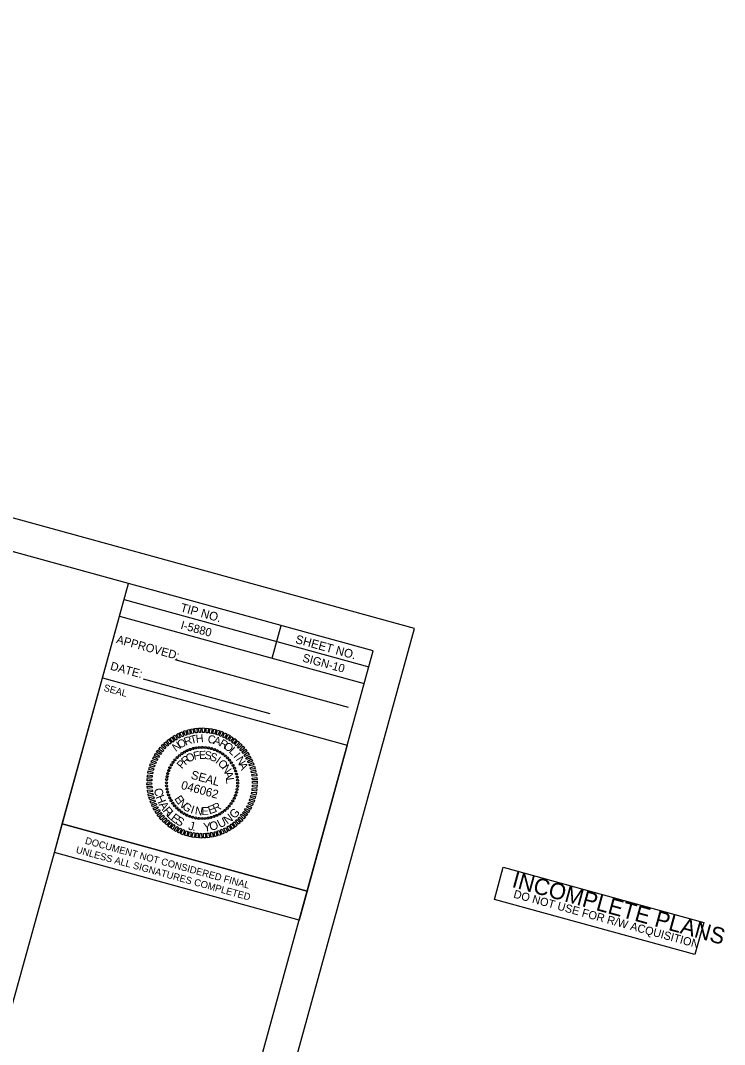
# Model space of a CAD drawing. Extents: x 1641195 to 1643343, y 841291 to 842800.
# Drawn here: x 1642824 to 1643343, y 842045 to 842799 of the extents above; entities that cross this region are included whole.
import ezdxf

# ---------------------------------------------------------------- set-up
doc = ezdxf.new("R2010")
doc.units = 0
for name, color, linetype in [('Default', 7, 'Continuous'), ('Level 11', 7, 'Continuous'), ('Level 18', 7, 'Continuous'), ('Level 2', 7, 'Continuous'), ('Level 3', 7, 'Continuous'), ('Level 6', 7, 'Continuous'), ('Level 60', 7, 'Continuous'), ('Level 8', 7, 'Continuous'), ('Level 9', 7, 'Continuous'), ('MILEMARKERS', 7, 'Continuous')]:
    doc.layers.add(name, color=color, linetype=linetype)

msp = doc.modelspace()

# ---------------------------------------------------------------- linework, layer by layer
at = {"layer": 'Level 18'}
for p, q in [((1642897.06, 842360.4), (1642903.68, 842384.45)), ((1642884.54, 842314.91), (1642897.06, 842360.4)), ((1642854.98, 842207.5), (1642884.54, 842314.91)), ((1643035.24, 842157.8), (1642854.98, 842207.5))]:
    msp.add_line(p, q, dxfattribs=at)
at = {"layer": 'Level 2'}
msp.add_lwpolyline([(1641195.06, 841738.58), (1642822.56, 841290.71), (1643114.42, 842351.28), (1641486.92, 842799.16)], close=True, dxfattribs=at)
at = {"layer": 'Level 3'}
msp.add_lwpolyline([(1643083.96, 842334.84), (1641638.42, 842732.64), (1641359.54, 841719.25), (1642805.09, 841321.44)], close=True, dxfattribs=at)
at = {"layer": 'Level 6'}
msp.add_lwpolyline([(1641792.98, 842690.11), (1641752.38, 842181.83), (1641755.46, 842119.79), (1641627.17, 841958.82), (1641586.62, 841880.3), (1641436.07, 841811.6), (1641408.39, 841755.09), (1641452.55, 841742.94), (1641576.94, 841708.71), (1641653.36, 841687.67), (1641800.35, 841636.49), (1641872.21, 841608.48), (1641936.45, 841597.66), (1642028.27, 841572.39), (1642158.19, 841597.22), (1642252.63, 841714.28), (1642387.32, 841813.32), (1642532.75, 841918.25), (1642817.65, 842071.9), (1642849.16, 842186.32), (1642903.68, 842384.45)], close=True, dxfattribs=at)
at = {"layer": 'Level 60'}
msp.add_lwpolyline([(1643173.29, 842151.82), (1643179.79, 842175.43), (1643327.45, 842134.79), (1643320.96, 842111.18)], close=True, dxfattribs=at)
at = {"layer": 'Level 8'}
for p, q in [((1642849.13, 842186.23), (1642854.96, 842207.41)), ((1642854.96, 842207.41), (1643035.24, 842157.8)), ((1643029.41, 842136.62), (1642849.13, 842186.23)), ((1643035.24, 842157.79), (1643029.41, 842136.61))]:
    msp.add_line(p, q, dxfattribs=at)
at = {"layer": 'Level 9'}
for p, q in [((1642884.54, 842314.91), (1642897.06, 842360.39)), ((1642953.58, 842263.45), (1642953.58, 842263.45)), ((1642955.81, 842263.74), (1642955.81, 842263.74)), ((1642958.09, 842263.8), (1642958.09, 842263.8)), ((1642960.43, 842263.64), (1642960.43, 842263.64)), ((1642962.68, 842263.38), (1642962.68, 842263.38)), ((1642939.48, 842256.27), (1642939.48, 842256.27)), ((1642941.21, 842257.77), (1642941.21, 842257.77)), ((1642943.04, 842259.19), (1642943.04, 842259.19)), ((1642944.96, 842260.37), (1642944.96, 842260.37)), ((1642947.02, 842261.46), (1642947.02, 842261.46)), ((1642949.12, 842262.27), (1642949.12, 842262.27)), ((1642951.34, 842262.94), (1642951.34, 842262.94)), ((1642964.92, 842262.86), (1642964.92, 842262.86)), ((1642967.11, 842262.14), (1642967.11, 842262.14)), ((1642969.2, 842261.22), (1642969.2, 842261.22)), ((1642971.21, 842260.22), (1642971.21, 842260.22)), ((1642973.16, 842258.97), (1642973.16, 842258.97)), ((1642974.95, 842257.54), (1642974.95, 842257.54)), ((1642976.66, 842256.02), (1642976.66, 842256.02)), ((1642934.27, 842248.81), (1642934.27, 842248.81)), ((1642935.28, 842250.82), (1642935.28, 842250.82)), ((1642936.53, 842252.76), (1642936.53, 842252.76)), ((1642937.96, 842254.56), (1642937.96, 842254.56)), ((1642978.16, 842254.28), (1642978.16, 842254.28)), ((1642979.58, 842252.46), (1642979.58, 842252.46)), ((1642980.76, 842250.54), (1642980.76, 842250.54)), ((1642981.85, 842248.48), (1642981.85, 842248.48)), ((1642932.12, 842242.29), (1642932.12, 842242.29)), ((1642932.64, 842244.53), (1642932.64, 842244.53)), ((1642933.36, 842246.72), (1642933.36, 842246.72)), ((1642982.67, 842246.38), (1642982.67, 842246.38)), ((1642983.34, 842244.16), (1642983.34, 842244.16)), ((1642983.84, 842241.92), (1642983.84, 842241.92)), ((1642931.69, 842237.7), (1642931.69, 842237.7)), ((1642931.76, 842235.42), (1642931.76, 842235.42)), ((1642931.86, 842240.03), (1642931.86, 842240.03)), ((1642932.05, 842233.18), (1642932.05, 842233.18)), ((1642957.95, 842237.55), (1642957.95, 842237.55)), ((1642984.03, 842235.07), (1642984.03, 842235.07)), ((1642984.13, 842239.69), (1642984.13, 842239.69)), ((1642984.2, 842237.41), (1642984.2, 842237.41)), ((1642932.55, 842230.95), (1642932.55, 842230.95)), ((1642933.23, 842228.73), (1642933.23, 842228.73)), ((1642934.04, 842226.63), (1642934.04, 842226.63)), ((1642981.62, 842226.3), (1642981.62, 842226.3)), ((1642982.53, 842228.39), (1642982.53, 842228.39)), ((1642983.25, 842230.58), (1642983.25, 842230.58)), ((1642983.78, 842232.82), (1642983.78, 842232.82)), ((1642935.13, 842224.57), (1642935.13, 842224.57)), ((1642936.31, 842222.64), (1642936.31, 842222.64)), ((1642937.73, 842220.82), (1642937.73, 842220.82)), ((1642939.23, 842219.09), (1642939.23, 842219.09)), ((1642976.41, 842218.84), (1642976.41, 842218.84)), ((1642977.93, 842220.55), (1642977.93, 842220.55)), ((1642979.36, 842222.34), (1642979.36, 842222.34)), ((1642980.62, 842224.29), (1642980.62, 842224.29)), ((1642940.94, 842217.57), (1642940.94, 842217.57)), ((1642942.74, 842216.14), (1642942.74, 842216.14)), ((1642944.68, 842214.88), (1642944.68, 842214.88)), ((1642946.69, 842213.88), (1642946.69, 842213.88)), ((1642948.78, 842212.97), (1642948.78, 842212.97)), ((1642950.97, 842212.24), (1642950.97, 842212.24)), ((1642953.21, 842211.72), (1642953.21, 842211.72)), ((1642955.47, 842211.47), (1642955.47, 842211.47)), ((1642957.8, 842211.3), (1642957.8, 842211.3)), ((1642960.08, 842211.36), (1642960.08, 842211.36)), ((1642962.31, 842211.66), (1642962.31, 842211.66)), ((1642964.55, 842212.16), (1642964.55, 842212.16)), ((1642966.77, 842212.83), (1642966.77, 842212.83)), ((1642968.87, 842213.64), (1642968.87, 842213.64)), ((1642970.93, 842214.73), (1642970.93, 842214.73)), ((1642972.85, 842215.92), (1642972.85, 842215.92)), ((1642974.68, 842217.34), (1642974.68, 842217.34))]:
    msp.add_line(p, q, dxfattribs=at)
for points in [[(1642884.54, 842314.91), (1643064.82, 842265.29), (1643035.27, 842157.88), (1642854.98, 842207.5)], [(1642936.32, 842267.72), (1642934.19, 842270.37), (1642935.64, 842271.4), (1642937.26, 842268.45)], [(1642938.58, 842269.19), (1642936.53, 842271.93), (1642938.1, 842272.77), (1642939.6, 842269.79)], [(1642940.71, 842270.53), (1642939.05, 842273.33), (1642940.58, 842274.23), (1642941.85, 842270.99)], [(1642943.14, 842271.58), (1642941.58, 842274.57), (1642943.22, 842275.28), (1642944.27, 842271.99)], [(1642945.45, 842272.61), (1642944.24, 842275.67), (1642945.8, 842276.29), (1642946.72, 842272.93)], [(1642948.01, 842273.3), (1642946.83, 842276.52), (1642948.61, 842276.92), (1642949.12, 842273.66)], [(1642950.5, 842273.96), (1642949.6, 842277.21), (1642951.35, 842277.52), (1642951.73, 842274.13)], [(1642953, 842274.45), (1642952.43, 842277.73), (1642954.11, 842277.94), (1642954.34, 842274.43)], [(1642955.69, 842274.62), (1642955.3, 842277.96), (1642956.99, 842278.01), (1642956.84, 842274.71)], [(1642958.29, 842274.66), (1642958.04, 842278.12), (1642959.85, 842278.04), (1642959.42, 842274.64)], [(1642960.86, 842274.59), (1642960.88, 842278.04), (1642962.59, 842277.76), (1642962.12, 842274.43)], [(1642963.37, 842274.27), (1642963.64, 842277.66), (1642965.42, 842277.42), (1642964.62, 842274.11)], [(1642965.97, 842273.88), (1642966.56, 842277.23), (1642968.22, 842276.75), (1642967.17, 842273.51)], [(1642968.39, 842273.2), (1642969.23, 842276.49), (1642970.89, 842276.01), (1642969.59, 842272.84)], [(1642970.88, 842272.4), (1642971.93, 842275.64), (1642973.52, 842274.91), (1642972.04, 842271.89)], [(1642973.21, 842271.37), (1642974.49, 842274.5), (1642976.1, 842273.81), (1642974.38, 842270.91)], [(1642975.65, 842270.15), (1642977, 842273.31), (1642978.62, 842272.47), (1642976.64, 842269.63)], [(1642977.91, 842268.87), (1642979.47, 842271.82), (1642980.91, 842270.91), (1642978.88, 842268.24)], [(1642928.88, 842260.61), (1642926.04, 842262.58), (1642927.2, 842263.95), (1642929.67, 842261.59)], [(1642930.49, 842262.68), (1642927.93, 842264.69), (1642929.09, 842266.06), (1642931.35, 842263.49)], [(1642932.26, 842264.55), (1642929.82, 842266.79), (1642931.19, 842267.95), (1642933.31, 842265.25)], [(1642934.3, 842266.18), (1642932.01, 842268.61), (1642933.35, 842269.83), (1642935.21, 842266.97)], [(1642979.95, 842267.37), (1642981.94, 842270.27), (1642983.2, 842269.29), (1642981.03, 842266.72)], [(1642981.99, 842265.83), (1642984.02, 842268.49), (1642985.41, 842267.38), (1642982.96, 842264.98)], [(1642984.02, 842264.06), (1642986.13, 842266.6), (1642987.42, 842265.35), (1642984.82, 842263.21)], [(1642985.64, 842262.19), (1642988.17, 842264.67), (1642989.21, 842263.27), (1642986.6, 842261.3)], [(1642924.63, 842254.14), (1642921.59, 842255.35), (1642922.39, 842256.98), (1642925.31, 842255.1)], [(1642925.91, 842256.4), (1642922.94, 842257.87), (1642923.72, 842259.45), (1642926.59, 842257.36)], [(1642927.3, 842258.64), (1642924.39, 842260.36), (1642925.45, 842261.76), (1642928.13, 842259.56)], [(1642987.33, 842260.14), (1642989.92, 842262.44), (1642990.95, 842260.99), (1642988.11, 842259.18)], [(1642988.85, 842258.07), (1642991.6, 842260.17), (1642992.51, 842258.65), (1642989.62, 842257.07)], [(1642990.22, 842255.83), (1642993.01, 842257.66), (1642993.91, 842256.13), (1642990.77, 842254.83)], [(1642921.99, 842246.78), (1642918.65, 842247.47), (1642919.1, 842249.19), (1642922.3, 842247.99)], [(1642922.69, 842249.3), (1642919.42, 842250.24), (1642919.95, 842251.89), (1642923.1, 842250.49)], [(1642923.56, 842251.66), (1642920.4, 842252.8), (1642921.04, 842254.47), (1642924.13, 842252.81)], [(1642991.52, 842253.56), (1642994.44, 842255.24), (1642995.15, 842253.6), (1642991.97, 842252.36)], [(1642992.54, 842251.19), (1642995.56, 842252.68), (1642996.15, 842250.97), (1642992.9, 842250.07)], [(1642993.32, 842248.78), (1642996.5, 842250.01), (1642997.07, 842248.25), (1642993.77, 842247.58)], [(1642920.9, 842239.17), (1642917.46, 842239.03), (1642917.6, 842240.83), (1642920.87, 842240.32)], [(1642921.07, 842241.72), (1642917.59, 842241.86), (1642917.88, 842243.62), (1642921.18, 842242.99)], [(1642921.39, 842244.23), (1642917.99, 842244.67), (1642918.33, 842246.42), (1642921.6, 842245.47)], [(1642994.07, 842246.21), (1642997.36, 842247.25), (1642997.61, 842245.52), (1642994.43, 842245.09)], [(1642994.52, 842243.77), (1642997.9, 842244.52), (1642998.14, 842242.74), (1642994.74, 842242.53)], [(1642994.82, 842241.16), (1642998.25, 842241.68), (1642998.4, 842239.97), (1642995.06, 842239.96)], [(1642920.88, 842236.59), (1642917.34, 842236.25), (1642917.47, 842238), (1642920.8, 842237.74)], [(1642921.07, 842233.95), (1642917.64, 842233.42), (1642917.49, 842235.14), (1642920.84, 842235.14)], [(1642994.82, 842233.38), (1642998.3, 842233.25), (1642998.01, 842231.49), (1642994.72, 842232.12)], [(1642994.99, 842235.93), (1642998.43, 842236.08), (1642998.29, 842234.28), (1642995.02, 842234.79)], [(1642995.01, 842238.52), (1642998.55, 842238.85), (1642998.42, 842237.1), (1642995.09, 842237.36)], [(1642921.37, 842231.33), (1642917.99, 842230.58), (1642917.75, 842232.37), (1642921.15, 842232.58)], [(1642921.83, 842228.9), (1642918.53, 842227.85), (1642918.28, 842229.59), (1642921.46, 842230.01)], [(1642922.57, 842226.33), (1642919.39, 842225.09), (1642918.82, 842226.86), (1642922.12, 842227.53)], [(1642993.21, 842225.81), (1642996.47, 842224.86), (1642995.94, 842223.22), (1642992.79, 842224.62)], [(1642993.91, 842228.33), (1642997.24, 842227.64), (1642996.8, 842225.91), (1642993.59, 842227.11)], [(1642994.51, 842230.87), (1642997.9, 842230.44), (1642997.56, 842228.69), (1642994.29, 842229.63)], [(1642923.35, 842223.92), (1642920.33, 842222.43), (1642919.74, 842224.14), (1642922.99, 842225.03)], [(1642924.37, 842221.55), (1642921.45, 842219.87), (1642920.74, 842221.51), (1642923.92, 842222.75)], [(1642925.67, 842219.27), (1642922.88, 842217.45), (1642921.98, 842218.98), (1642925.12, 842220.28)], [(1642927.04, 842217.03), (1642924.29, 842214.93), (1642923.38, 842216.46), (1642926.27, 842218.04)], [(1642989.98, 842218.7), (1642992.95, 842217.24), (1642992.17, 842215.66), (1642989.3, 842217.74)], [(1642991.26, 842220.96), (1642994.3, 842219.75), (1642993.5, 842218.12), (1642990.58, 842220)], [(1642992.33, 842223.44), (1642995.49, 842222.31), (1642994.85, 842220.64), (1642991.76, 842222.29)], [(1642928.56, 842214.97), (1642925.97, 842212.66), (1642924.94, 842214.12), (1642927.78, 842215.92)], [(1642930.25, 842212.92), (1642927.72, 842210.43), (1642926.68, 842211.83), (1642929.29, 842213.81)], [(1642931.87, 842211.04), (1642929.77, 842208.51), (1642928.47, 842209.76), (1642931.07, 842211.9)], [(1642983.63, 842210.56), (1642986.07, 842208.31), (1642984.7, 842207.16), (1642982.58, 842209.86)], [(1642985.4, 842212.43), (1642987.96, 842210.42), (1642986.8, 842209.05), (1642984.55, 842211.62)], [(1642987.01, 842214.5), (1642989.85, 842212.53), (1642988.69, 842211.15), (1642986.22, 842213.51)], [(1642988.6, 842216.47), (1642991.5, 842214.75), (1642990.44, 842213.35), (1642987.77, 842215.54)], [(1642933.91, 842209.28), (1642931.87, 842206.62), (1642930.48, 842207.73), (1642932.93, 842210.12)], [(1642935.94, 842207.73), (1642933.95, 842204.84), (1642932.69, 842205.81), (1642934.86, 842208.39)], [(1642937.98, 842206.24), (1642936.42, 842203.29), (1642934.98, 842204.2), (1642937.01, 842206.86)], [(1642940.25, 842204.95), (1642938.89, 842201.79), (1642937.28, 842202.64), (1642939.25, 842205.48)], [(1642942.69, 842203.73), (1642941.4, 842200.61), (1642939.79, 842201.29), (1642941.51, 842204.2)], [(1642945.01, 842202.71), (1642943.97, 842199.47), (1642942.37, 842200.2), (1642943.85, 842203.22)], [(1642972.75, 842203.53), (1642974.31, 842200.54), (1642972.67, 842199.82), (1642971.62, 842203.11)], [(1642975.18, 842204.58), (1642976.84, 842201.78), (1642975.31, 842200.87), (1642974.04, 842204.11)], [(1642977.31, 842205.92), (1642979.36, 842203.18), (1642977.79, 842202.34), (1642976.29, 842205.32)], [(1642979.57, 842207.39), (1642981.7, 842204.74), (1642980.25, 842203.71), (1642978.63, 842206.66)], [(1642981.59, 842208.92), (1642983.88, 842206.5), (1642982.54, 842205.28), (1642980.68, 842208.13)], [(1642947.51, 842201.9), (1642946.66, 842198.61), (1642945, 842199.09), (1642946.3, 842202.27)], [(1642949.92, 842201.23), (1642949.33, 842197.87), (1642947.67, 842198.35), (1642948.72, 842201.59)], [(1642952.52, 842200.83), (1642952.25, 842197.45), (1642950.47, 842197.69), (1642951.27, 842200.99)], [(1642955.03, 842200.51), (1642955.01, 842197.06), (1642953.3, 842197.34), (1642953.78, 842200.67)], [(1642957.6, 842200.45), (1642957.85, 842196.98), (1642956.04, 842197.07), (1642956.48, 842200.47)], [(1642960.2, 842200.48), (1642960.59, 842197.14), (1642958.9, 842197.09), (1642959.05, 842200.4)], [(1642962.89, 842200.66), (1642963.46, 842197.38), (1642961.78, 842197.16), (1642961.55, 842200.68)], [(1642965.4, 842201.15), (1642966.29, 842197.9), (1642964.54, 842197.59), (1642964.16, 842200.98)], [(1642967.89, 842201.81), (1642969.06, 842198.59), (1642967.28, 842198.18), (1642966.77, 842201.44)], [(1642970.44, 842202.5), (1642971.65, 842199.44), (1642970.09, 842198.81), (1642969.17, 842202.18)]]:
    msp.add_lwpolyline(points, close=True, dxfattribs=at)
for centre, major_axis in [((1642949.14, 842262.26), (-0.253, 0.709)), ((1642951.33, 842262.93), (-0.19, 0.729)), ((1642953.57, 842263.41), (-0.126, 0.742)), ((1642955.84, 842263.7), (-0.061, 0.751)), ((1642958.12, 842263.78), (0.005, 0.753)), ((1642960.41, 842263.67), (0.071, 0.75)), ((1642962.67, 842263.35), (0.136, 0.741)), ((1642964.9, 842262.84), (0.2, 0.726)), ((1642939.53, 842256.22), (-0.529, 0.536)), ((1642941.22, 842257.76), (-0.48, 0.58)), ((1642943.05, 842259.14), (-0.428, 0.62)), ((1642944.99, 842260.35), (-0.372, 0.655)), ((1642947.02, 842261.4), (-0.314, 0.685)), ((1642967.08, 842262.14), (0.262, 0.706)), ((1642969.19, 842261.25), (0.323, 0.68)), ((1642971.21, 842260.18), (0.381, 0.65)), ((1642973.13, 842258.94), (0.436, 0.614)), ((1642974.94, 842257.53), (0.488, 0.574)), ((1642976.62, 842255.97), (0.536, 0.529)), ((1642934.25, 842248.8), (-0.68, 0.323)), ((1642935.32, 842250.82), (-0.65, 0.381)), ((1642936.56, 842252.74), (-0.614, 0.436)), ((1642937.97, 842254.55), (-0.574, 0.488)), ((1642978.15, 842254.28), (0.58, 0.48)), ((1642979.53, 842252.45), (0.62, 0.428)), ((1642980.75, 842250.51), (0.655, 0.372)), ((1642981.79, 842248.48), (0.685, 0.314)), ((1642931.83, 842240.02), (-0.75, 0.071)), ((1642932.15, 842242.28), (-0.741, 0.136)), ((1642932.66, 842244.51), (-0.726, 0.2)), ((1642933.36, 842246.69), (-0.706, 0.262)), ((1642982.65, 842246.36), (0.709, 0.253)), ((1642983.32, 842244.17), (0.729, 0.19)), ((1642983.81, 842241.93), (0.742, 0.126)), ((1642931.72, 842237.73), (-0.753, 0.005)), ((1642931.8, 842235.44), (-0.751, -0.061)), ((1642932.09, 842233.17), (-0.742, -0.126)), ((1642983.74, 842232.82), (0.741, -0.136)), ((1642984.06, 842235.09), (0.75, -0.071)), ((1642984.09, 842239.66), (0.751, 0.061)), ((1642984.17, 842237.38), (0.753, -0.005)), ((1642932.57, 842230.94), (-0.729, -0.19)), ((1642933.24, 842228.75), (-0.709, -0.253)), ((1642934.1, 842226.63), (-0.685, -0.314)), ((1642935.14, 842224.59), (-0.655, -0.372)), ((1642981.64, 842226.31), (0.68, -0.323)), ((1642982.53, 842228.42), (0.706, -0.262)), ((1642983.23, 842230.59), (0.726, -0.2)), ((1642936.36, 842222.65), (-0.62, -0.428)), ((1642937.74, 842220.83), (-0.58, -0.48)), ((1642939.28, 842219.13), (-0.536, -0.529)), ((1642940.95, 842217.58), (-0.488, -0.574)), ((1642974.67, 842217.35), (0.48, -0.58)), ((1642976.37, 842218.88), (0.529, -0.536)), ((1642977.92, 842220.56), (0.574, -0.488)), ((1642979.33, 842222.36), (0.614, -0.436)), ((1642980.57, 842224.29), (0.65, -0.381)), ((1642942.76, 842216.17), (-0.436, -0.614)), ((1642944.68, 842214.93), (-0.381, -0.65)), ((1642946.7, 842213.86), (-0.323, -0.68)), ((1642948.81, 842212.97), (-0.262, -0.706)), ((1642950.99, 842212.27), (-0.2, -0.726)), ((1642953.22, 842211.76), (-0.136, -0.741)), ((1642955.48, 842211.44), (-0.071, -0.75)), ((1642957.77, 842211.33), (-0.005, -0.753)), ((1642960.06, 842211.41), (0.061, -0.751)), ((1642962.33, 842211.69), (0.126, -0.742)), ((1642964.56, 842212.17), (0.19, -0.729)), ((1642966.75, 842212.85), (0.253, -0.709)), ((1642968.87, 842213.71), (0.314, -0.685)), ((1642970.91, 842214.75), (0.372, -0.655)), ((1642972.84, 842215.97), (0.428, -0.62))]:
    msp.add_ellipse(centre, major_axis=major_axis, ratio=0.999708, dxfattribs=at)
at = {"layer": 'MILEMARKERS'}
for p, q in [((1642897.06, 842360.39), (1642903.68, 842384.44)), ((1642900.44, 842372.67), (1643013, 842341.68)), ((1642897.06, 842360.39), (1643077.34, 842310.76)), ((1643009.62, 842329.41), (1643016.25, 842353.47)), ((1643009.62, 842329.41), (1643016.25, 842353.47)), ((1643013, 842341.68), (1643080.72, 842323.04)), ((1643083.96, 842334.84), (1643083.96, 842334.84)), ((1643083.96, 842334.84), (1643083.96, 842334.84)), ((1643083.96, 842334.84), (1643083.96, 842334.84)), ((1643083.96, 842334.84), (1643083.96, 842334.84)), ((1643083.96, 842334.84), (1643083.96, 842334.84)), ((1643083.96, 842334.84), (1643083.96, 842334.84)), ((1643083.96, 842334.84), (1643083.96, 842334.84)), ((1643083.96, 842334.84), (1643083.96, 842334.84)), ((1642937.75, 842328.53), (1643065.61, 842293.35)), ((1642914.46, 842314.3), (1643007.77, 842288.62))]:
    msp.add_line(p, q, dxfattribs=at)

# ---------------------------------------------------------------- texts
at = {"layer": 'Default'}
for s, rotation, p in [('C', 281.81323, (1642922.37, 842233.1)), ('H', 291.257, (1642923.58, 842227.32)), ('A', 301.09681, (1642925.83, 842221.6)), ('R', 309.80945, (1642928.61, 842216.92)), ('G', 46.41316, (1642981.8, 842210.76)), ('L', 317.18168, (1642931.5, 842213.33)), ('E', 323.36583, (1642934.26, 842210.62)), ('S', 330.3725, (1642937.73, 842207.93)), ('U', 26.04812, (1642971, 842204.14)), ('N', 35.84222, (1642976.49, 842206.84)), ('J', 347.64547, (1642947.43, 842203.26)), ('.', 352.82736, (1642950.57, 842202.45)), ('Y', 6.85593, (1642959.29, 842201.7)), ('O', 14.65466, (1642964.14, 842202.22))]:
    msp.add_text(s, height=6.27, rotation=rotation, dxfattribs=at).set_placement(p)
at = {"layer": 'Level 11'}
for s, p in [('APPROVED:', (1642894.34, 842340.75)), ('DATE:', (1642889.88, 842321.09))]:
    msp.add_text(s, height=6.11, rotation=344.60835, dxfattribs=at).set_placement(p)
at = {"layer": 'Level 60'}
for s, height, p in [('INCOMPLETE PLANS', 12.0025, (1643185.52, 842161.1)), ('DO NOT USE FOR R/W ACQUISITION', 6.0012, (1643186.86, 842153.22))]:
    msp.add_text(s, height=height, rotation=344.61341, dxfattribs=at).set_placement(p)
at = {"layer": 'Level 8'}
for s, p in [('DOCUMENT NOT CONSIDERED FINAL', (1642871.38, 842192.86)), ('UNLESS ALL SIGNATURES COMPLETED', (1642864.63, 842186.19))]:
    msp.add_text(s, height=5.1412, rotation=344.61341, dxfattribs=at).set_placement(p)
at = {"layer": 'Level 9'}
for s, height, rotation, p in [('R', 5.9, 20.63388, (1642945.86, 842264.94)), ('T', 5.9, 13.43315, (1642949.88, 842266.29)), ('H', 5.9, 6.23286, (1642953.6, 842267.12)), ('C', 5.9, 351.83325, (1642961.82, 842267.17)), ('A', 5.9, 344.6337, (1642965.9, 842266.44)), ('N', 5.9, 35.03688, (1642938.48, 842260.36)), ('O', 5.9, 27.83512, (1642941.56, 842262.7)), ('R', 5.9, 330.23448, (1642970.1, 842265.15)), ('O', 5.9, 323.03454, (1642973.3, 842263.52)), ('L', 5.9, 315.83425, (1642977.27, 842260.5)), ('R', 5.9, 39.65303, (1642945.57, 842250.34)), ('O', 5.9, 30.29462, (1642947.98, 842252.36)), ('F', 5.9, 11.58041, (1642952.09, 842254.49)), ('E', 5.9, 2.22444, (1642955.72, 842255.18)), ('S', 5.9, 352.86899, (1642959.49, 842255.35)), ('S', 5.9, 343.51378, (1642963.15, 842254.46)), ('I', 5.9, 324.80298, (1642967.32, 842252.64)), ('I', 5.9, 308.63352, (1642980.75, 842257.02)), ('N', 5.9, 301.43229, (1642982.53, 842254.89)), ('P', 5.9, 49.01227, (1642943.12, 842247.51)), ('O', 5.9, 315.44686, (1642969.17, 842251.41)), ('N', 5.9, 306.08999, (1642972.04, 842248.51)), ('A', 5.9, 294.23053, (1642984.75, 842251.14)), ('SEAL', 6.273, 344.61338, (1642949.24, 842240.87)), ('A', 5.9, 287.37364, (1642974.25, 842245.14)), ('L', 5.9, 278.01423, (1642975.33, 842241.14)), ('046062', 6.275, 344.61338, (1642942, 842233.31)), ('E', 5.9, 303.89027, (1642937.27, 842225.96)), ('N', 5.9, 313.24733, (1642939.6, 842222.45)), ('G', 5.9, 322.60362, (1642942.87, 842219.18)), ('I', 5.9, 341.31458, (1642949.01, 842215.55)), ('N', 5.9, 350.66977, (1642952.36, 842214.53)), ('E', 5.9, 0.02514, (1642957.53, 842213.85)), ('E', 5.9, 18.73747, (1642963.41, 842214.45)), ('R', 5.9, 28.09479, (1642967.62, 842215.91))]:
    msp.add_text(s, height=height, rotation=rotation, dxfattribs=at).set_placement(p)
at = {"layer": 'MILEMARKERS'}
for s, height, p in [('TIP NO.', 6.358, (1642941.47, 842364.02)), ('I-5880', 6.11, (1642941.73, 842351.27)), ('SHEET NO.', 6.358, (1643026.23, 842340.68)), ('SIGN-10', 6.11, (1643031.41, 842327.12)), ('SEAL', 5.094, (1642885.09, 842305.51))]:
    msp.add_text(s, height=height, rotation=344.60835, dxfattribs=at).set_placement(p)

doc.saveas('drawing.dxf')
